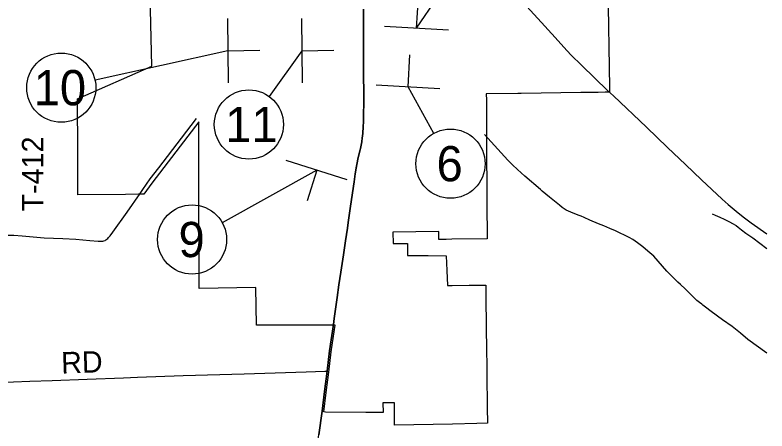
# Model space of a CAD drawing. Extents: x 40529 to 41139, y 15164 to 15584.
# Drawn here: x 40677.8 to 40737.7, y 15358.4 to 15391.5 of the extents above; entities that cross this region are included whole.
import ezdxf

# ---------------------------------------------------------------- set-up
doc = ezdxf.new("R2010")
doc.units = 0
for name, color, linetype in [('Default', 7, 'Continuous'), ('GM_X_Corporation', 7, 'Continuous'), ('GM_X_State_Route', 7, 'Continuous'), ('GM_X_Township_Road', 7, 'Continuous'), ('GM_X_Township_Road_Text', 7, 'Continuous'), ('SH_Data', 7, 'Continuous'), ('SH_Text', 7, 'Continuous')]:
    doc.layers.add(name, color=color, linetype=linetype)

msp = doc.modelspace()

# ---------------------------------------------------------------- linework, layer by layer
at = {"layer": 'Default'}
for p, q in [((40709.776, 15390.449), (40709.922, 15392.993)), ((40694.728, 15391.196), (40694.795, 15386.101)), ((40700.612, 15391.196), (40700.679, 15386.101)), ((40707.232, 15390.595), (40712.32, 15390.302)), ((40694.761, 15388.648), (40697.309, 15388.682)), ((40700.646, 15388.648), (40703.194, 15388.682)), ((40709.094, 15385.784), (40709.24, 15388.328)), ((40706.55, 15385.93), (40711.637, 15385.638)), ((40704.263, 15378.383), (40699.4, 15379.908)), ((40701.831, 15379.146), (40701.069, 15376.714))]:
    msp.add_line(p, q, dxfattribs=at)
at = {"layer": 'GM_X_Corporation'}
msp.add_lwpolyline([(40724.997, 15393.81), (40725.116, 15385.709), (40725.132, 15385.341), (40724.769, 15385.336), (40724.231, 15385.329), (40722.846, 15385.31), (40718.098, 15385.244), (40717.837, 15385.24), (40715.324, 15385.205), (40715.327, 15384.719), (40715.333, 15383.349), (40715.339, 15382.141), (40715.341, 15381.888), (40715.342, 15381.635), (40715.367, 15376.586), (40715.381, 15373.688), (40712.587, 15373.654), (40712.119, 15373.648), (40711.551, 15373.641), (40711.548, 15374.264), (40707.892, 15374.219), (40707.908, 15373.321), (40709.048, 15373.325), (40709.06, 15372.372), (40709.736, 15372.363), (40710.693, 15372.352), (40712.118, 15372.334), (40712.181, 15371.162), (40712.244, 15369.992), (40712.281, 15369.992), (40712.613, 15369.993), (40713.962, 15369.999), (40715.273, 15370.004), (40715.29, 15368.699), (40715.297, 15368.143), (40715.304, 15367.587), (40715.311, 15367.032), (40715.314, 15366.585), (40715.321, 15366.08), (40715.326, 15365.428), (40715.337, 15364.838), (40715.341, 15364.627), (40715.356, 15363.82), (40715.372, 15363.024), (40715.368, 15362.455), (40715.376, 15361.886), (40715.383, 15361.318), (40715.393, 15360.976), (40715.4, 15360.281), (40715.413, 15359.029), (40714.56, 15359.01), (40712.635, 15358.967), (40708.021, 15358.864), (40708.019, 15359.877), (40708.017, 15360.647), (40707.102, 15360.653), (40707.104, 15359.883), (40706.895, 15359.885), (40705.727, 15359.893), (40702.541, 15359.914), (40702.386, 15359.928), (40702.582, 15361.477), (40702.787, 15363.099), (40702.99, 15364.712), (40703.286, 15366.825), (40703.124, 15366.825), (40701.443, 15366.825), (40700.358, 15366.825), (40699.264, 15366.824), (40698.159, 15366.824), (40697.953, 15366.824), (40697.045, 15366.824), (40696.984, 15369.812), (40692.469, 15369.745), (40692.465, 15372.192), (40692.459, 15377.262), (40692.454, 15381.108), (40692.453, 15381.848), (40692.451, 15382.978), (40691.58, 15381.849), (40688.7, 15378.126), (40688.075, 15377.231), (40687.981, 15377.231), (40687.877, 15377.23), (40687.773, 15377.229), (40687.657, 15377.228), (40686.611, 15377.221), (40682.832, 15377.195), (40682.826, 15378.765), (40682.824, 15379.332), (40682.818, 15380.681), (40682.811, 15382.478), (40682.81, 15382.82), (40682.809, 15383.086), (40682.802, 15384.64), (40682.802, 15384.811), (40688.711, 15387.419), (40688.541, 15394.18)], dxfattribs=at)
at = {"layer": 'GM_X_State_Route'}
msp.add_line((40705.542, 15391.073), (40705.543, 15391.959), dxfattribs=at)
for points in [[(40717.65, 15393.167), (40719.427, 15391.208), (40720.801, 15389.687), (40721.482, 15388.923), (40722.059, 15388.317), (40722.914, 15387.46), (40724.967, 15385.486)], [(40705.566, 15385.106), (40705.558, 15386.875), (40705.546, 15387.605), (40705.551, 15388.058), (40705.549, 15388.704), (40705.546, 15389.819), (40705.548, 15390.098), (40705.548, 15390.47), (40705.542, 15391.073)], [(40724.967, 15385.486), (40725.433, 15385.055), (40728.061, 15382.561), (40729.747, 15380.951), (40731.162, 15379.599), (40732.448, 15378.381), (40733.258, 15377.609), (40734.079, 15376.85), (40734.568, 15376.419), (40735.355, 15375.762), (40735.867, 15375.359), (40736.39, 15374.97), (40737.651, 15374.082)], [(40705.411, 15381.437), (40705.447, 15381.692), (40705.492, 15382.058), (40705.537, 15382.624), (40705.548, 15382.987), (40705.566, 15385.036), (40705.566, 15385.106)], [(40704.116, 15373.528), (40704.193, 15374.035), (40704.27, 15374.535), (40704.335, 15374.989), (40704.522, 15376.276), (40704.804, 15378.215), (40704.898, 15378.864), (40705.007, 15379.506), (40705.027, 15379.602), (40705.14, 15380.143), (40705.282, 15380.771), (40705.304, 15380.867), (40705.406, 15381.405), (40705.411, 15381.437)], [(40703.154, 15366.886), (40703.219, 15367.356), (40703.449, 15369.037), (40703.585, 15370.031), (40703.736, 15371.044), (40703.948, 15372.422), (40704.116, 15373.528)], [(40702.254, 15359.996), (40702.451, 15361.543), (40702.655, 15363.164), (40702.858, 15364.775), (40703.154, 15366.886)], [(40696.317, 15346.421), (40696.935, 15347.316), (40698.387, 15349.371), (40699.262, 15350.579), (40700.402, 15352.171), (40700.771, 15352.711), (40700.981, 15353.019), (40701.111, 15353.243), (40701.236, 15353.509), (40701.335, 15353.785), (40701.409, 15354.062), (40701.473, 15354.336), (40701.518, 15354.614), (40701.61, 15355.355), (40701.63, 15355.507), (40701.785, 15356.643), (40701.905, 15357.47), (40701.995, 15358.117), (40702.254, 15359.996)]]:
    msp.add_lwpolyline(points, dxfattribs=at)
at = {"layer": 'GM_X_Township_Road'}
for points in [[(40687.777, 15377.281), (40688.001, 15377.622), (40688.585, 15378.451), (40689.261, 15379.341), (40691.085, 15381.699), (40692.264, 15383.268)], [(40721.684, 15375.981), (40721.521, 15376.08), (40721.359, 15376.185), (40721.134, 15376.356), (40720.344, 15377.009), (40719.77, 15377.482), (40719.626, 15377.607), (40718.378, 15378.664), (40717.806, 15379.192), (40717.405, 15379.569), (40717.037, 15379.937), (40715.167, 15381.983)], [(40677.214, 15373.991), (40677.738, 15373.977), (40678.393, 15373.934), (40680.151, 15373.779), (40681.636, 15373.717), (40682.675, 15373.651), (40683.787, 15373.568), (40684.429, 15373.513), (40684.623, 15373.506), (40684.716, 15373.503), (40684.802, 15373.506), (40684.895, 15373.52), (40684.989, 15373.554), (40685.061, 15373.603), (40685.141, 15373.662), (40685.207, 15373.724), (40685.273, 15373.785), (40685.394, 15373.922), (40685.619, 15374.218), (40686.752, 15375.814), (40687.777, 15377.281)], [(40737.651, 15364.611), (40736.132, 15365.695), (40735.554, 15366.183), (40734.881, 15366.71), (40734.112, 15367.261), (40733.202, 15367.915), (40732.749, 15368.255), (40732.552, 15368.41), (40732.475, 15368.483), (40732.295, 15368.624), (40732.072, 15368.791), (40731.892, 15368.966), (40731.417, 15369.442), (40731.143, 15369.703), (40730.77, 15370.054), (40730.552, 15370.255), (40730.209, 15370.589), (40729.696, 15371.107), (40728.649, 15372.319), (40728.175, 15372.718), (40727.777, 15373.065), (40727.344, 15373.381), (40726.981, 15373.625), (40726.694, 15373.788), (40726.317, 15373.989), (40725.976, 15374.151), (40725.597, 15374.323), (40725.139, 15374.503), (40724.685, 15374.713), (40724.248, 15374.893), (40723.559, 15375.18), (40723.096, 15375.373), (40722.865, 15375.484), (40722.699, 15375.553), (40722.22, 15375.743), (40721.867, 15375.882), (40721.684, 15375.981)], [(40733.282, 15375.682), (40733.542, 15375.577), (40733.911, 15375.41), (40734.251, 15375.257), (40734.402, 15375.183), (40734.668, 15375.048), (40734.913, 15374.913), (40735.198, 15374.737), (40735.351, 15374.63), (40735.632, 15374.414), (40735.969, 15374.149), (40736.515, 15373.759), (40737.651, 15372.91)], [(40676.389, 15362.279), (40678.998, 15362.363), (40680.769, 15362.426), (40683.564, 15362.535), (40686.454, 15362.643), (40687.572, 15362.694), (40691.206, 15362.837), (40696.053, 15362.961), (40700.994, 15363.115), (40702.483, 15363.159), (40702.655, 15363.164)]]:
    msp.add_lwpolyline(points, dxfattribs=at)
at = {"layer": 'SH_Data'}
for p, q in [((40709.776, 15390.449), (40717.103, 15401.133)), ((40694.761, 15388.648), (40684.192, 15386.302)), ((40700.646, 15388.648), (40698.038, 15385.015)), ((40711.144, 15382.072), (40709.094, 15385.784)), ((40701.831, 15379.146), (40694.318, 15374.972))]:
    msp.add_line(p, q, dxfattribs=at)
msp.add_lwpolyline([(40705.543, 15391.959), (40705.542, 15391.073), (40705.548, 15390.47), (40705.548, 15390.098), (40705.546, 15389.819), (40705.549, 15388.704), (40705.551, 15388.09), (40705.558, 15386.875), (40705.566, 15385.106), (40705.548, 15382.987), (40705.537, 15382.624), (40705.492, 15382.058), (40705.447, 15381.692), (40705.411, 15381.437), (40705.406, 15381.405), (40705.304, 15380.867), (40705.282, 15380.771), (40705.14, 15380.143), (40705.027, 15379.602), (40704.898, 15378.864), (40704.804, 15378.215), (40704.522, 15376.276), (40704.335, 15374.989), (40704.27, 15374.535), (40704.193, 15374.035), (40704.116, 15373.528), (40703.948, 15372.422), (40703.736, 15371.044), (40703.585, 15370.031), (40703.449, 15369.037), (40703.219, 15367.356), (40703.154, 15366.886), (40702.858, 15364.775), (40702.655, 15363.164), (40702.451, 15361.543), (40702.254, 15359.996), (40701.995, 15358.117)], dxfattribs=at)
at = {"layer": 'SH_Text'}
for centre in [(40681.508, 15385.706), (40696.434, 15382.781), (40712.473, 15379.665), (40691.914, 15373.636)]:
    msp.add_circle(centre, 2.75, dxfattribs=at)

# ---------------------------------------------------------------- texts
at = {"layer": 'GM_X_Township_Road_Text'}
for s, rotation, p in [('T-412', 90, (40680.082, 15375.866)), ('RD', 1.97477, (40681.527, 15362.973))]:
    msp.add_text(s, height=1.7063, rotation=rotation, dxfattribs=at).set_placement(p)
at = {"layer": 'SH_Text'}
for s, p in [('10', (40679.315, 15384.306)), ('11', (40694.555, 15381.381)), ('6', (40711.364, 15378.265)), ('9', (40690.836, 15372.236))]:
    msp.add_text(s, height=2.8, dxfattribs=at).set_placement(p)

doc.saveas('drawing.dxf')
